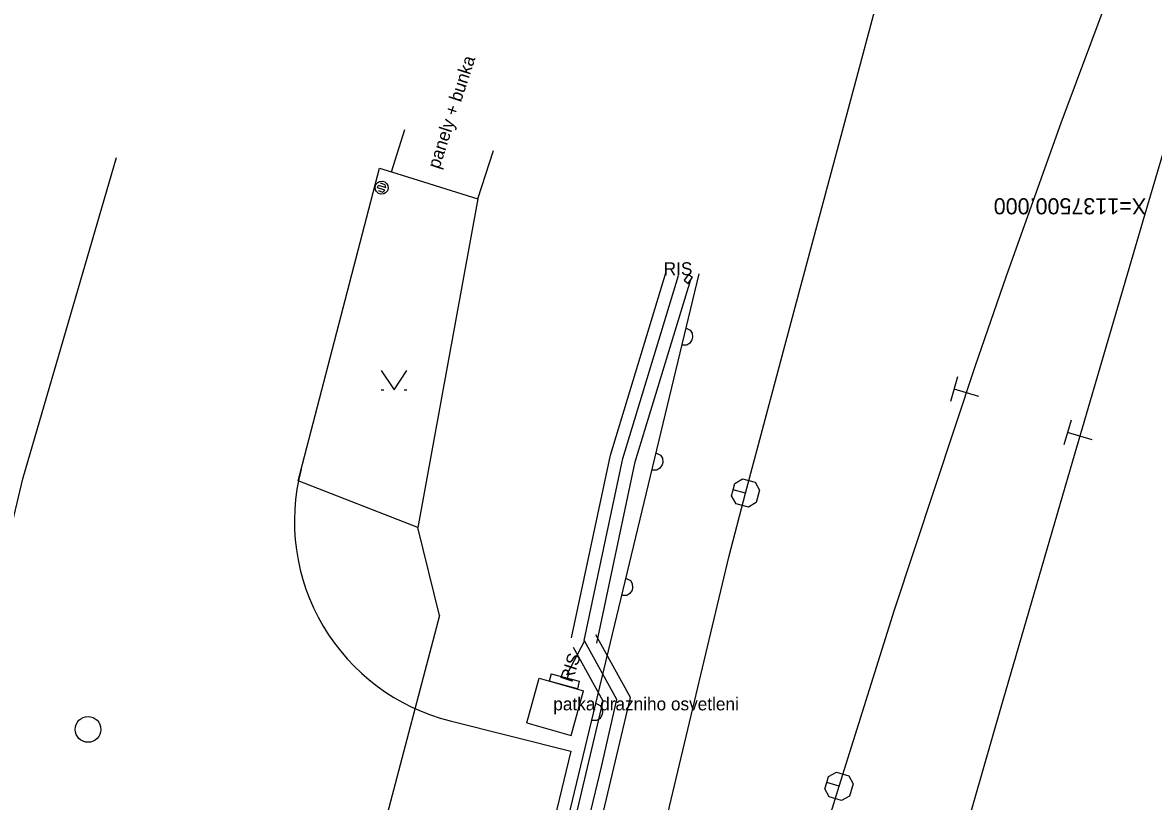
# Model space of a CAD drawing. Extents: x -733601 to -733291, y -1137892 to -1137187.
# Drawn here: x -733445.37 to -733401.43, y -1137523.14 to -1137492.88 of the extents above; entities that cross this region are included whole.
import ezdxf

# ---------------------------------------------------------------- set-up
doc = ezdxf.new("R2010")
doc.units = 0
for name, color, linetype in [('Krizky_Hektom_sit', 7, 'Continuous'), ('SIT_PROJ', 7, 'Continuous'), ('SIT_PUV_BUS', 7, 'Continuous'), ('SIT_PUV_ZELEZNICE', 7, 'Continuous')]:
    doc.layers.add(name, color=color, linetype=linetype)

msp = doc.modelspace()

# ---------------------------------------------------------------- linework, layer by layer
at = {"layer": 'SIT_PROJ'}
for points in [[(-733424.042, -1137516.776), (-733422.531, -1137509.687), (-733420.362, -1137502.562)], [(-733423.553, -1137516.88), (-733422.046, -1137509.812), (-733419.883, -1137502.707)], [(-733423.064, -1137516.985), (-733421.562, -1137509.937), (-733419.405, -1137502.853)], [(-733472.116, -1137618.354), (-733450.389, -1137531.821), (-733445.369, -1137510.61)], [(-733427.159, -1137551.881), (-733428.074, -1137550.062), (-733424.377, -1137530.206), (-733421.746, -1137519.1), (-733423.097, -1137516.67)], [(-733428.052, -1137552.331), (-733429.119, -1137550.211), (-733425.355, -1137529.999), (-733422.808, -1137519.247), (-733423.971, -1137517.156)], [(-733427.369, -1137552.561), (-733428.596, -1137550.137), (-733427.81, -1137546.252), (-733426.105, -1137537.1), (-733424.866, -1137530.103), (-733422.883, -1137521.79), (-733422.277, -1137519.173), (-733423.543, -1137516.897), (-733424.238, -1137518.238)], [(-733428.759, -1137520.007), (-733424.071, -1137521.184), (-733426.163, -1137529.882), (-733428.201, -1137541.484)]]:
    msp.add_lwpolyline(points, dxfattribs=at)
msp.add_circle((-733442.83, -1137520.341), 0.5, dxfattribs=at)
msp.add_arc((-733426.811, -1137512.248), 8, 165.3947, 255.9059, dxfattribs=at)
at = {"layer": 'SIT_PUV_BUS'}
for p, q in [((-733431.04, -1137498.68), (-733430.52, -1137497.03)), ((-733427.68, -1137499.73), (-733427.08, -1137497.85)), ((-733445.37, -1137510.61), (-733441.73, -1137498.12)), ((-733434.67, -1137510.68), (-733431.5, -1137498.53)), ((-733431.5, -1137498.53), (-733431.04, -1137498.68)), ((-733431.04, -1137498.68), (-733427.68, -1137499.73)), ((-733431.673, -1137499.26), (-733431.642, -1137499.165)), ((-733431.642, -1137499.165), (-733431.564, -1137499.086)), ((-733431.564, -1137499.086), (-733431.501, -1137499.053)), ((-733431.501, -1137499.053), (-733431.39, -1137499.037)), ((-733431.279, -1137499.178), (-733431.469, -1137499.116)), ((-733431.39, -1137499.037), (-733431.295, -1137499.068)), ((-733431.295, -1137499.068), (-733431.216, -1137499.146)), ((-733431.262, -1137499.289), (-733431.279, -1137499.178)), ((-733431.216, -1137499.146), (-733431.183, -1137499.209)), ((-733431.657, -1137499.371), (-733431.673, -1137499.26)), ((-733431.624, -1137499.434), (-733431.657, -1137499.371)), ((-733431.545, -1137499.512), (-733431.624, -1137499.434)), ((-733431.578, -1137499.291), (-733431.547, -1137499.196)), ((-733431.293, -1137499.384), (-733431.578, -1137499.291)), ((-733431.561, -1137499.402), (-733431.371, -1137499.464)), ((-733431.547, -1137499.196), (-733431.262, -1137499.289)), ((-733431.45, -1137499.543), (-733431.545, -1137499.512)), ((-733431.339, -1137499.527), (-733431.45, -1137499.543)), ((-733431.371, -1137499.464), (-733431.293, -1137499.384)), ((-733431.276, -1137499.494), (-733431.339, -1137499.527)), ((-733431.198, -1137499.415), (-733431.276, -1137499.494)), ((-733431.167, -1137499.32), (-733431.198, -1137499.415)), ((-733431.183, -1137499.209), (-733431.167, -1137499.32)), ((-733427.68, -1137499.73), (-733430.01, -1137512.5)), ((-733419.1, -1137502.64), (-733425.66, -1137529.91)), ((-733419.49, -1137502.66), (-733419.66, -1137502.89)), ((-733419.49, -1137502.66), (-733419.34, -1137502.77)), ((-733419.66, -1137502.89), (-733419.51, -1137503.01)), ((-733419.51, -1137503.01), (-733419.34, -1137502.77)), ((-733419.608, -1137504.73), (-733419.425, -1137504.825)), ((-733419.425, -1137504.825), (-733419.352, -1137504.946)), ((-733419.445, -1137505.335), (-733419.566, -1137505.408)), ((-733419.361, -1137505.2), (-733419.445, -1137505.335)), ((-733419.338, -1137505.103), (-733419.361, -1137505.2)), ((-733419.352, -1137504.946), (-733419.338, -1137505.103)), ((-733419.566, -1137505.408), (-733419.772, -1137505.41)), ((-733431.44, -1137506.4), (-733430.94, -1137507.15)), ((-733430.94, -1137507.15), (-733430.44, -1137506.4)), ((-733431.44, -1137507.15), (-733431.34, -1137507.15)), ((-733430.54, -1137507.15), (-733430.44, -1137507.15)), ((-733420.768, -1137509.59), (-733420.585, -1137509.685)), ((-733420.585, -1137509.685), (-733420.512, -1137509.806)), ((-733420.521, -1137510.06), (-733420.605, -1137510.195)), ((-733420.498, -1137509.963), (-733420.521, -1137510.06)), ((-733420.512, -1137509.806), (-733420.498, -1137509.963)), ((-733420.726, -1137510.268), (-733420.932, -1137510.27)), ((-733420.605, -1137510.195), (-733420.726, -1137510.268)), ((-733430.01, -1137512.5), (-733434.67, -1137510.68)), ((-733429.17, -1137515.92), (-733430.01, -1137512.5)), ((-733421.938, -1137514.46), (-733421.755, -1137514.555)), ((-733421.755, -1137514.555), (-733421.682, -1137514.676)), ((-733421.691, -1137514.93), (-733421.775, -1137515.065)), ((-733421.668, -1137514.833), (-733421.691, -1137514.93)), ((-733421.682, -1137514.676), (-733421.668, -1137514.833)), ((-733421.896, -1137515.138), (-733422.102, -1137515.14)), ((-733421.775, -1137515.065), (-733421.896, -1137515.138)), ((-733429.17, -1137515.92), (-733434.52, -1137536.22)), ((-733425.78, -1137520.09), (-733425.3, -1137518.35)), ((-733425.3, -1137518.35), (-733423.57, -1137518.84)), ((-733424.83, -1137518.18), (-733424.91, -1137518.47)), ((-733423.81, -1137518.76), (-733424.91, -1137518.47)), ((-733424.83, -1137518.18), (-733423.74, -1137518.47)), ((-733423.74, -1137518.47), (-733423.81, -1137518.76)), ((-733424.06, -1137520.58), (-733423.57, -1137518.84)), ((-733423.108, -1137519.32), (-733422.925, -1137519.415)), ((-733422.861, -1137519.79), (-733422.945, -1137519.925)), ((-733422.925, -1137519.415), (-733422.852, -1137519.536)), ((-733422.838, -1137519.693), (-733422.861, -1137519.79)), ((-733422.852, -1137519.536), (-733422.838, -1137519.693)), ((-733425.78, -1137520.09), (-733424.06, -1137520.58)), ((-733423.066, -1137519.998), (-733423.272, -1137520)), ((-733422.945, -1137519.925), (-733423.066, -1137519.998))]:
    msp.add_line(p, q, dxfattribs=at)
at = {"layer": 'SIT_PUV_ZELEZNICE'}
for p, q in [((-733409.037, -1137506.645), (-733409.316, -1137507.605)), ((-733408.216, -1137507.403), (-733409.177, -1137507.125)), ((-733404.626, -1137508.327), (-733404.904, -1137509.288)), ((-733403.805, -1137509.086), (-733404.765, -1137508.808)), ((-733417.826, -1137511.27), (-733417.761, -1137511.028)), ((-733417.761, -1137511.028), (-733417.697, -1137510.787)), ((-733417.278, -1137511.157), (-733417.761, -1137511.028)), ((-733417.697, -1137510.787), (-733417.391, -1137510.61)), ((-733417.391, -1137510.61), (-733416.908, -1137510.739)), ((-733416.908, -1137510.739), (-733416.731, -1137511.045)), ((-733416.731, -1137511.045), (-733416.86, -1137511.528)), ((-733417.649, -1137511.576), (-733417.826, -1137511.27)), ((-733417.166, -1137511.705), (-733417.649, -1137511.576)), ((-733416.86, -1137511.528), (-733417.166, -1137511.705)), ((-733414.051, -1137522.165), (-733413.738, -1137521.999)), ((-733413.738, -1137521.999), (-733413.26, -1137522.145)), ((-733414.197, -1137522.643), (-733414.124, -1137522.404)), ((-733414.124, -1137522.404), (-733414.051, -1137522.165)), ((-733413.646, -1137522.55), (-733414.124, -1137522.404)), ((-733413.26, -1137522.145), (-733413.094, -1137522.457)), ((-733413.094, -1137522.457), (-733413.241, -1137522.936)), ((-733414.031, -1137522.955), (-733414.197, -1137522.643)), ((-733413.553, -1137523.101), (-733414.031, -1137522.955)), ((-733413.241, -1137522.936), (-733413.553, -1137523.101))]:
    msp.add_line(p, q, dxfattribs=at)
for points in [[(-733432.613, -1137592.177), (-733430.241, -1137582.464), (-733428.195, -1137572.675), (-733426.476, -1137562.825), (-733425.101, -1137553.045), (-733425.086, -1137552.922), (-733424.525, -1137548.394), (-733423.804, -1137543.005), (-733422.199, -1137533.135), (-733420.237, -1137523.33), (-733417.92, -1137513.602), (-733417.278, -1137511.157), (-733415.349, -1137503.939), (-733412.766, -1137494.278), (-733410.183, -1137484.617), (-733407.6, -1137474.957), (-733405.017, -1137465.296), (-733402.434, -1137455.636), (-733401.342, -1137451.549), (-733399.798, -1137445.99), (-733397.493, -1137438.369), (-733396.877, -1137436.426), (-733393.987, -1137427.309)], [(-733424.195, -1137560.031), (-733423.136, -1137555.989), (-733422.64, -1137554.102), (-733420.028, -1137544.45), (-733419.6, -1137542.91), (-733417.303, -1137534.828), (-733414.464, -1137525.239), (-733413.695, -1137522.711), (-733413.646, -1137522.55), (-733411.495, -1137515.69), (-733408.347, -1137506.199), (-733407.141, -1137502.714), (-733405.019, -1137496.769), (-733401.513, -1137487.404), (-733399.59, -1137482.49), (-733397.847, -1137478.1), (-733394.158, -1137468.806), (-733394.03, -1137468.485), (-733390.544, -1137459.482), (-733387.094, -1137450.096), (-733383.809, -1137440.651), (-733380.689, -1137431.15), (-733380.109, -1137429.318)], [(-733424.808, -1137581.736), (-733423.595, -1137577.27), (-733420.948, -1137567.626), (-733420.168, -1137564.801), (-733418.278, -1137557.99), (-733415.583, -1137548.36), (-733412.864, -1137538.736), (-733410.121, -1137529.12), (-733408.737, -1137524.299), (-733407.354, -1137519.51), (-733404.564, -1137509.907), (-733401.749, -1137500.312), (-733398.91, -1137490.723)]]:
    msp.add_lwpolyline(points, dxfattribs=at)

# ---------------------------------------------------------------- texts
at = {"layer": 'Krizky_Hektom_sit'}
msp.add_text('X=1137500.000', height=0.625, rotation=180, dxfattribs=at).set_placement((-733401.71, -1137499.7))
at = {"layer": 'SIT_PUV_BUS'}
for s, p in [('panely + bunka', (-733429.18, -1137498.59)), ('RIS', (-733424.02, -1137518.54))]:
    msp.add_text(s, height=0.5, rotation=72, dxfattribs=at).set_placement(p)
for s, p in [('RIS', (-733420.46, -1137502.69)), ('patka drazniho osvetleni', (-733424.75, -1137519.6))]:
    msp.add_text(s, height=0.5, dxfattribs=at).set_placement(p)

doc.saveas('drawing.dxf')
